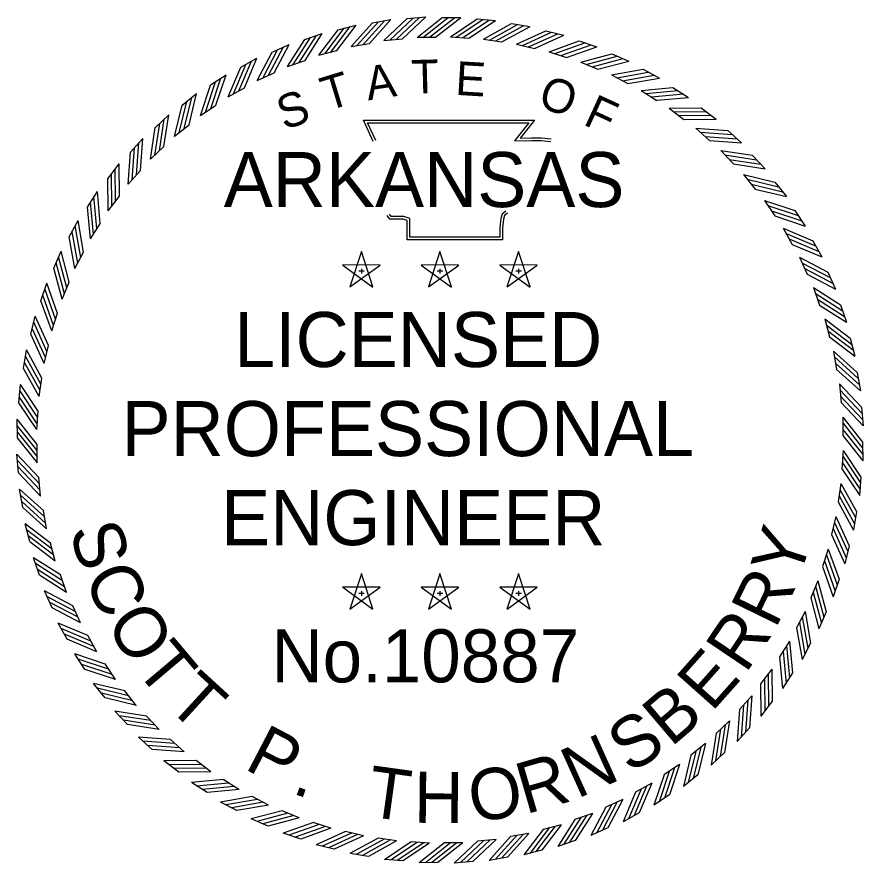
# Model space of a CAD drawing. Extents: x 155 to 3386, y 68 to 2138.
# Drawn here: x 2988.4 to 3236.8, y 328.7 to 577.1 of the extents above; entities that cross this region are included whole.
import ezdxf

# ---------------------------------------------------------------- set-up
doc = ezdxf.new("R2010")
doc.units = 0
doc.layers.add('STAMP', color=7, linetype='Continuous')

msp = doc.modelspace()

# ---------------------------------------------------------------- linework, layer by layer
at = {"layer": 'STAMP'}
for p, q in [((3102.98, 576.62), (3108.39, 577.12)), ((3113.28, 576.93), (3118.72, 576.93)), ((3123.47, 576.52), (3128.9, 576.12)), ((3082.74, 573.35), (3088.01, 574.74)), ((3092.79, 575.41), (3098.15, 576.35)), ((3133.64, 575.2), (3139.01, 574.35)), ((3072.9, 570.48), (3078.03, 572.29)), ((3143.67, 573.04), (3148.95, 571.76)), ((3063.33, 566.8), (3068.29, 569.03)), ((3086.49, 568.42), (3091.86, 569.36)), ((3096.11, 570.18), (3101.54, 570.68)), ((3105.85, 571.14), (3111.31, 571.14)), ((3115.64, 571.29), (3121.08, 570.89)), ((3125.41, 570.63), (3130.79, 569.79)), ((3135.08, 569.17), (3140.38, 567.88)), ((3153.48, 570.07), (3158.64, 568.35)), ((3077.04, 565.87), (3082.31, 567.25)), ((3144.61, 566.92), (3149.78, 565.2)), ((3054.09, 562.34), (3058.85, 564.97)), ((3067.83, 562.54), (3072.97, 564.36)), ((3163.02, 566.29), (3168.02, 564.15)), ((3153.91, 563.89), (3158.93, 561.74)), ((3172.21, 561.74), (3177.02, 559.19)), ((3045.25, 557.14), (3049.78, 560.15)), ((3058.93, 558.47), (3063.9, 560.71)), ((3162.94, 560.1), (3167.76, 557.54)), ((3036.88, 551.22), (3041.14, 554.6)), ((3050.39, 553.68), (3055.17, 556.32)), ((3171.62, 555.57), (3176.21, 552.63)), ((3180.99, 556.44), (3185.57, 553.51)), ((3042.29, 548.2), (3046.82, 551.23)), ((3179.89, 550.35), (3184.23, 547.04)), ((3189.31, 550.44), (3193.63, 547.14)), ((3029.02, 544.63), (3032.98, 548.35)), ((3034.66, 542.07), (3038.93, 545.46)), ((3187.71, 544.46), (3191.76, 540.8)), ((3197.1, 543.77), (3201.14, 540.13)), ((3021.73, 537.42), (3025.37, 541.45)), ((3027.56, 535.33), (3031.54, 539.06)), ((3195.01, 537.94), (3198.74, 533.96)), ((3204.31, 536.48), (3208.04, 532.52)), ((3015.06, 529.62), (3018.36, 533.95)), ((3021.04, 528.03), (3024.7, 532.07)), ((3201.75, 530.84), (3205.14, 526.57)), ((3210.9, 528.62), (3214.28, 524.36)), ((3009.06, 521.31), (3011.99, 525.89)), ((3015.15, 520.21), (3018.46, 524.54)), ((3207.88, 523.21), (3210.91, 518.68)), ((3216.82, 520.25), (3219.84, 515.72)), ((3003.76, 512.52), (3006.31, 517.33)), ((3009.93, 511.93), (3012.87, 516.53)), ((3213.36, 515.11), (3216, 510.33)), ((3222.02, 511.41), (3224.66, 506.65)), ((2999.21, 503.33), (3001.35, 508.34)), ((3005.4, 503.25), (3007.96, 508.07)), ((3089.5, 508.28), (3086.1, 497.84)), ((3092.89, 497.84), (3089.51, 508.29)), ((3112.58, 508.28), (3109.18, 497.84)), ((3115.97, 497.84), (3112.59, 508.29)), ((3135.66, 508.28), (3132.26, 497.84)), ((3139.05, 497.84), (3135.67, 508.29)), ((3218.16, 506.57), (3220.39, 501.6)), ((3094.99, 504.29), (3084.01, 504.3)), ((3084.02, 504.29), (3092.9, 497.83)), ((3086.11, 497.84), (3095, 504.29)), ((3088.72, 502.54), (3090.35, 502.54)), ((3089.51, 503.13), (3089.51, 501.75)), ((3118.07, 504.29), (3107.08, 504.3)), ((3107.09, 504.29), (3115.97, 497.83)), ((3109.19, 497.84), (3118.08, 504.29)), ((3111.8, 502.54), (3113.43, 502.54)), ((3112.59, 503.13), (3112.59, 501.75)), ((3141.15, 504.29), (3130.16, 504.3)), ((3130.17, 504.29), (3139.05, 497.83)), ((3132.27, 497.84), (3141.16, 504.29)), ((3134.88, 502.54), (3136.51, 502.54)), ((3135.67, 503.13), (3135.67, 501.75)), ((3226.48, 502.17), (3228.71, 497.21)), ((2995.43, 493.8), (2997.15, 498.96)), ((3001.61, 494.23), (3003.76, 499.24)), ((3222.23, 497.67), (3224.05, 492.53)), ((3230.16, 492.6), (3231.98, 487.47)), ((2998.58, 484.92), (3000.3, 490.1)), ((2992.46, 483.98), (2993.74, 489.27)), ((3225.55, 488.46), (3226.94, 483.19)), ((3233.04, 482.76), (3234.42, 477.49)), ((2996.33, 475.4), (2997.62, 480.7)), ((2990.3, 473.96), (2991.15, 479.33)), ((3228.1, 479.01), (3229.05, 473.64)), ((3235.09, 472.71), (3236.04, 467.35)), ((2994.87, 465.72), (2995.71, 471.11)), ((2988.98, 463.79), (2989.38, 469.21)), ((3229.86, 469.39), (3230.36, 463.96)), ((3236.31, 462.52), (3236.81, 457.11)), ((2994.21, 455.96), (2994.61, 461.4)), ((3230.82, 459.65), (3230.87, 454.19)), ((2988.5, 453.54), (2988.45, 458.98)), ((3236.68, 452.28), (3236.73, 446.83)), ((2994.36, 446.17), (2994.31, 451.62)), ((3230.97, 449.86), (3230.57, 444.42)), ((2988.88, 443.29), (2988.38, 448.71)), ((2995.32, 436.43), (2994.82, 441.86)), ((3230.32, 440.09), (3229.47, 434.71)), ((3236.2, 442.03), (3235.8, 436.6)), ((2990.09, 433.11), (2989.15, 438.47)), ((2997.08, 426.8), (2996.14, 432.17)), ((3228.86, 430.42), (3227.57, 425.12)), ((3234.88, 431.86), (3234.04, 426.49)), ((2992.15, 423.06), (2990.76, 428.32)), ((2999.63, 417.35), (2998.25, 422.63)), ((3226.6, 420.89), (3224.88, 415.72)), ((3232.73, 421.83), (3231.44, 416.55)), ((2995.02, 413.22), (2993.21, 418.35)), ((3002.96, 408.15), (3001.14, 413.29)), ((3089.5, 413.66), (3086.1, 403.21)), ((3092.89, 403.22), (3089.51, 413.67)), ((3112.58, 413.66), (3109.18, 403.21)), ((3115.97, 403.22), (3112.59, 413.67)), ((3135.66, 413.66), (3132.26, 403.21)), ((3139.05, 403.22), (3135.67, 413.67)), ((3223.57, 411.59), (3221.43, 406.57)), ((3229.75, 412.02), (3228.03, 406.86)), ((2998.7, 403.64), (2996.47, 408.61)), ((3094.99, 409.67), (3084.01, 409.68)), ((3084.02, 409.67), (3092.9, 403.21)), ((3086.11, 403.22), (3095, 409.67)), ((3088.72, 407.92), (3090.35, 407.92)), ((3089.51, 408.5), (3089.51, 407.12)), ((3118.07, 409.67), (3107.08, 409.68)), ((3107.09, 409.67), (3115.97, 403.21)), ((3109.19, 403.22), (3118.08, 409.67)), ((3111.8, 407.92), (3113.43, 407.92)), ((3112.59, 408.5), (3112.59, 407.12)), ((3141.15, 409.67), (3130.16, 409.68)), ((3130.17, 409.67), (3139.05, 403.21)), ((3132.27, 403.22), (3141.16, 409.67)), ((3134.88, 407.92), (3136.51, 407.92)), ((3135.67, 408.5), (3135.67, 407.12)), ((3007.03, 399.25), (3004.79, 404.22)), ((3219.78, 402.56), (3217.23, 397.74)), ((3225.97, 402.48), (3223.83, 397.48)), ((3003.16, 394.41), (3000.53, 399.17)), ((3011.82, 390.71), (3009.18, 395.48)), ((3215.25, 393.88), (3212.31, 389.29)), ((3221.42, 393.29), (3218.88, 388.48)), ((3008.36, 385.57), (3005.35, 390.1)), ((3017.3, 382.6), (3014.27, 387.14)), ((3210.03, 385.61), (3206.72, 381.27)), ((3216.13, 384.51), (3213.19, 379.93)), ((3014.28, 377.19), (3010.9, 381.45)), ((3023.43, 374.97), (3020.04, 379.25)), ((3204.14, 377.79), (3200.48, 373.74)), ((3210.13, 376.19), (3206.82, 371.87)), ((3020.87, 369.33), (3017.15, 373.3)), ((3030.17, 367.88), (3026.44, 371.85)), ((3197.62, 370.49), (3193.65, 366.76)), ((3203.46, 368.4), (3199.81, 364.36)), ((3028.08, 362.04), (3024.05, 365.69)), ((3037.47, 361.36), (3033.43, 365.02)), ((3190.53, 363.75), (3186.25, 360.36)), ((3196.17, 361.19), (3192.2, 357.46)), ((3035.88, 355.37), (3031.55, 358.68)), ((3045.29, 355.47), (3040.96, 358.78)), ((3182.9, 357.62), (3178.36, 354.59)), ((3053.57, 350.25), (3048.97, 353.19)), ((3188.31, 354.6), (3184.05, 351.22)), ((3044.19, 349.37), (3039.61, 352.31)), ((3174.79, 352.14), (3170.02, 349.5)), ((3062.25, 345.72), (3057.43, 348.27)), ((3179.93, 348.68), (3175.4, 345.66)), ((3052.98, 344.08), (3048.17, 346.62)), ((3166.25, 347.34), (3161.28, 345.11)), ((3071.27, 341.93), (3066.26, 344.07)), ((3157.35, 343.27), (3152.21, 341.45)), ((3171.09, 343.48), (3166.33, 340.84)), ((3062.17, 339.53), (3057.16, 341.67)), ((3080.58, 338.9), (3075.4, 340.62)), ((3090.1, 336.64), (3084.8, 337.93)), ((3148.15, 339.95), (3142.87, 338.56)), ((3161.86, 339.02), (3156.9, 336.79)), ((3071.7, 335.75), (3066.54, 337.47)), ((3099.78, 335.18), (3094.39, 336.03)), ((3129.07, 335.64), (3123.64, 335.14)), ((3138.7, 337.4), (3133.33, 336.45)), ((3081.52, 332.77), (3076.23, 334.06)), ((3109.54, 334.53), (3104.1, 334.93)), ((3119.33, 334.68), (3113.88, 334.63)), ((3152.28, 335.34), (3147.15, 333.52)), ((3091.54, 330.62), (3086.17, 331.46)), ((3142.44, 332.46), (3137.18, 331.08)), ((3101.71, 329.3), (3096.29, 329.7)), ((3111.96, 328.82), (3106.52, 328.77)), ((3122.21, 329.19), (3116.79, 328.69)), ((3132.39, 330.41), (3127.03, 329.46))]:
    msp.add_line(p, q, dxfattribs=at)
for points in [[(3096.11, 570.17), (3102.97, 576.62)], [(3097.85, 570.32), (3104.71, 576.76)], [(3099.73, 570.53), (3106.59, 576.98)], [(3101.54, 570.68), (3108.4, 577.13)], [(3105.85, 571.13), (3113.27, 576.92)], [(3107.6, 571.12), (3115.02, 576.91)], [(3109.49, 571.16), (3116.91, 576.95)], [(3111.3, 571.14), (3118.72, 576.93)], [(3115.63, 571.29), (3123.46, 576.52)], [(3080.55, 566.81), (3086.25, 574.3)], [(3082.3, 567.26), (3088.01, 574.74)], [(3086.48, 568.41), (3092.79, 575.4)], [(3088.21, 568.7), (3094.51, 575.69)], [(3090.06, 569.07), (3096.37, 576.06)], [(3091.85, 569.37), (3098.15, 576.36)], [(3117.38, 571.14), (3125.21, 576.37)], [(3119.27, 571.04), (3127.09, 576.27)], [(3121.07, 570.89), (3128.9, 576.12)], [(3125.4, 570.63), (3133.63, 575.2)], [(3127.13, 570.34), (3135.36, 574.91)], [(3129, 570.09), (3137.23, 574.65)], [(3130.79, 569.79), (3139.02, 574.36)], [(3071.25, 563.78), (3076.32, 571.71)], [(3072.96, 564.36), (3078.03, 572.3)], [(3077.03, 565.86), (3082.74, 573.35)], [(3078.73, 566.29), (3084.44, 573.78)], [(3135.08, 569.17), (3143.66, 573.04)], [(3136.77, 568.74), (3145.36, 572.61)], [(3138.62, 568.33), (3147.2, 572.2)], [(3140.38, 567.89), (3148.96, 571.76)], [(3063.9, 560.71), (3068.29, 569.04)], [(3067.83, 562.54), (3072.89, 570.47)], [(3069.48, 563.11), (3074.55, 571.04)], [(3144.6, 566.92), (3153.47, 570.06)], [(3146.26, 566.35), (3155.13, 569.5)], [(3148.06, 565.79), (3156.94, 568.94)], [(3058.93, 558.47), (3063.32, 566.79)], [(3060.53, 559.17), (3064.92, 567.49)], [(3062.24, 559.98), (3066.63, 568.31)], [(3149.78, 565.2), (3158.65, 568.35)], [(3053.57, 555.46), (3057.26, 564.12)], [(3055.16, 556.32), (3058.85, 564.98)], [(3153.91, 563.88), (3163.01, 566.29)], [(3155.51, 563.18), (3164.61, 565.59)], [(3157.26, 562.48), (3166.37, 564.88)], [(3158.92, 561.75), (3168.03, 564.15)], [(3050.39, 553.67), (3054.09, 562.33)], [(3051.93, 554.51), (3055.63, 563.17)], [(3162.93, 560.09), (3172.2, 561.74)], [(3045.3, 550.23), (3048.26, 559.17)], [(3046.82, 551.23), (3049.78, 560.16)], [(3164.47, 559.26), (3173.74, 560.9)], [(3166.16, 558.41), (3175.43, 560.06)], [(3167.75, 557.55), (3177.02, 559.19)], [(3042.28, 548.19), (3045.25, 557.13)], [(3043.75, 549.15), (3046.71, 558.09)], [(3038.92, 545.46), (3041.14, 554.61)], [(3171.61, 555.57), (3180.98, 556.44)], [(3173.07, 554.61), (3182.45, 555.49)], [(3174.69, 553.63), (3184.06, 554.5)], [(3036.04, 543.14), (3038.25, 552.29)], [(3037.49, 544.34), (3039.71, 553.49)], [(3176.21, 552.64), (3185.58, 553.51)], [(3034.65, 542.06), (3036.87, 551.21)], [(3179.88, 550.35), (3189.3, 550.44)], [(3181.27, 549.27), (3190.68, 549.37)], [(3030.2, 537.83), (3031.65, 547.13)], [(3031.53, 539.06), (3032.99, 548.36)], [(3093.01, 540.51), (3090.11, 546.79), (3140.29, 546.82), (3136.09, 541.56), (3139.5, 541.6), (3142.35, 541.64), (3145.2, 541.33)], [(3182.79, 548.16), (3192.21, 548.25)], [(3184.22, 547.04), (3193.64, 547.14)], [(3027.56, 535.32), (3029.01, 544.62)], [(3028.85, 536.51), (3030.3, 545.81)], [(3093.73, 540.85), (3091.35, 546), (3138.64, 546.03), (3134.43, 540.74), (3139.51, 540.81), (3142.31, 540.84), (3145.11, 540.54)], [(3187.7, 544.46), (3197.09, 543.78)], [(3188.99, 543.27), (3198.38, 542.59)], [(3190.42, 542.03), (3199.81, 541.35)], [(3023.47, 530.74), (3024.15, 540.13)], [(3024.69, 532.07), (3025.37, 541.46)], [(3191.75, 540.81), (3201.14, 540.13)], [(3021.04, 528.02), (3021.72, 537.41)], [(3022.23, 529.31), (3022.91, 538.7)], [(3195, 537.94), (3204.31, 536.49)], [(3196.19, 536.65), (3205.49, 535.2)], [(3197.51, 535.3), (3206.81, 533.85)], [(3017.34, 523.11), (3017.25, 532.52)], [(3018.46, 524.54), (3018.36, 533.95)], [(3198.74, 533.97), (3208.04, 532.51)], [(3015.15, 520.2), (3015.06, 529.61)], [(3016.23, 521.58), (3016.13, 531)], [(3201.75, 530.85), (3210.89, 528.63)], [(3202.82, 529.46), (3211.97, 527.25)], [(3204.03, 528.01), (3213.18, 525.79)], [(3011.87, 515.01), (3011, 524.38)], [(3012.86, 516.52), (3011.99, 525.9)], [(3205.14, 526.58), (3214.29, 524.36)], [(3010.89, 513.39), (3010.01, 522.76)], [(3207.88, 523.22), (3216.81, 520.25)], [(3208.83, 521.75), (3217.77, 518.79)], [(3009.93, 511.93), (3009.06, 521.3)], [(3132.38, 519.49), (3131.52, 518.79), (3131.24, 517.75), (3130.96, 515.15), (3130.96, 511.68), (3102.94, 511.68), (3102.94, 516.36), (3102.94, 517.4), (3101.81, 517.75), (3097.82, 517.75), (3097.12, 518.83)], [(3131.88, 520.1), (3130.82, 519.24), (3130.46, 517.9), (3130.16, 515.19), (3130.16, 512.47), (3103.74, 512.47), (3103.74, 516.36), (3103.74, 517.99), (3101.93, 518.54), (3098.25, 518.54), (3097.78, 519.26)], [(3209.92, 520.2), (3218.85, 517.24)], [(3007.95, 508.07), (3006.31, 517.34)], [(3210.91, 518.68), (3219.84, 515.72)], [(3007.09, 506.48), (3005.44, 515.75)], [(3213.36, 515.11), (3222.02, 511.42)], [(3005.41, 503.25), (3003.76, 512.52)], [(3006.24, 504.79), (3004.6, 514.06)], [(3214.19, 513.57), (3222.85, 509.87)], [(3215.14, 511.93), (3223.8, 508.24)], [(3216, 510.34), (3224.66, 506.65)], [(3003.75, 499.24), (3001.35, 508.34)], [(3002.32, 495.83), (2999.92, 504.93)], [(3003.02, 497.58), (3000.62, 506.68)], [(3218.15, 506.58), (3226.47, 502.18)], [(3218.85, 504.97), (3227.18, 500.58)], [(3001.62, 494.22), (2999.21, 503.32)], [(3219.67, 503.26), (3227.99, 498.87)], [(3220.39, 501.6), (3228.72, 497.21)], [(2999.71, 488.38), (2996.56, 497.25)], [(3000.3, 490.09), (2997.15, 498.97)], [(3222.22, 497.67), (3230.15, 492.61)], [(2999.15, 486.57), (2996, 495.45)], [(3222.79, 496.02), (3230.72, 490.95)], [(2998.58, 484.92), (2995.44, 493.79)], [(3223.46, 494.25), (3231.39, 489.18)], [(3224.05, 492.54), (3231.98, 487.47)], [(2997.17, 478.94), (2993.3, 487.52)], [(2997.61, 480.69), (2993.74, 489.28)], [(3225.54, 488.47), (3233.03, 482.76)], [(2996.76, 477.09), (2992.89, 485.67)], [(3225.97, 486.77), (3233.46, 481.06)], [(3226.49, 484.95), (3233.98, 479.25)], [(2996.33, 475.39), (2992.46, 483.98)], [(3226.94, 483.2), (3234.43, 477.49)], [(2995.41, 469.32), (2990.85, 477.55)], [(2995.71, 471.1), (2991.14, 479.34)], [(3228.09, 479.02), (3235.08, 472.71)], [(3228.38, 477.29), (3235.37, 470.99)], [(2995.16, 467.44), (2990.59, 475.68)], [(3228.75, 475.44), (3235.74, 469.13)], [(2994.87, 465.72), (2990.3, 473.95)], [(3229.05, 473.65), (3236.04, 467.35)], [(2994.46, 459.58), (2989.23, 467.41)], [(2994.61, 461.39), (2989.38, 469.22)], [(3229.86, 469.39), (3236.3, 462.53)], [(3230, 467.65), (3236.45, 460.79)], [(2994.36, 457.7), (2989.13, 465.52)], [(3230.22, 465.77), (3236.66, 458.91)], [(2994.21, 455.95), (2988.98, 463.78)], [(3230.36, 463.96), (3236.81, 457.1)], [(3230.82, 459.65), (3236.67, 452.28)], [(2994.31, 451.62), (2988.45, 458.99)], [(2994.31, 449.8), (2988.45, 457.17)], [(3230.82, 457.9), (3236.67, 450.53)], [(2994.37, 447.92), (2988.51, 455.29)], [(3230.88, 456.01), (3236.73, 448.64)], [(2994.37, 446.16), (2988.51, 453.53)], [(3230.88, 454.2), (3236.73, 446.83)], [(3230.97, 449.87), (3236.2, 442.04)], [(2994.82, 441.85), (2988.37, 448.71)], [(3230.82, 448.12), (3236.05, 440.29)], [(2994.97, 440.05), (2988.52, 446.91)], [(2995.18, 438.17), (2988.74, 445.03)], [(3230.73, 446.23), (3235.96, 438.41)], [(2995.33, 436.42), (2988.88, 443.29)], [(3230.58, 444.43), (3235.81, 436.6)], [(3230.31, 440.1), (3234.88, 431.87)], [(2996.13, 432.17), (2989.14, 438.47)], [(3230.03, 438.37), (3234.59, 430.14)], [(2996.43, 430.38), (2989.44, 436.68)], [(2996.8, 428.52), (2989.81, 434.83)], [(3229.77, 436.5), (3234.34, 428.27)], [(2997.09, 426.8), (2990.1, 433.1)], [(3229.47, 434.71), (3234.04, 426.48)], [(3228.85, 430.42), (3232.72, 421.84)], [(2998.24, 422.62), (2990.76, 428.33)], [(3228.42, 428.73), (3232.29, 420.14)], [(2998.69, 420.86), (2991.2, 426.57)], [(3227.57, 425.12), (3231.44, 416.54)], [(3228.02, 426.88), (3231.89, 418.3)], [(2999.21, 419.05), (2991.72, 424.75)], [(2999.64, 417.35), (2992.15, 423.05)], [(3226.6, 420.9), (3229.75, 412.03)], [(3001.14, 413.28), (2993.2, 418.35)], [(3225.47, 417.44), (3228.62, 408.56)], [(3226.03, 419.24), (3229.18, 410.37)], [(3001.72, 411.57), (2993.79, 416.63)], [(3224.89, 415.72), (3228.03, 406.85)], [(3002.39, 409.8), (2994.46, 414.87)], [(3002.96, 408.14), (2995.03, 413.21)], [(3222.86, 409.99), (3225.27, 400.89)], [(3223.57, 411.59), (3225.97, 402.49)], [(3004.79, 404.21), (2996.46, 408.61)], [(3222.16, 408.24), (3224.56, 399.13)], [(3005.52, 402.55), (2997.19, 406.95)], [(3006.33, 400.85), (2998.01, 405.24)], [(3221.43, 406.58), (3223.84, 397.47)], [(3007.03, 399.24), (2998.71, 403.64)], [(3219.78, 402.57), (3221.42, 393.3)], [(3218.94, 401.03), (3220.59, 391.76)], [(3009.18, 395.48), (3000.52, 399.17)], [(3010.04, 393.88), (3001.38, 397.58)], [(3217.23, 397.75), (3218.88, 388.48)], [(3218.1, 399.34), (3219.74, 390.07)], [(3010.99, 392.25), (3002.33, 395.94)], [(3011.83, 390.71), (3003.17, 394.4)], [(3215.25, 393.89), (3216.13, 384.52)], [(3014.27, 387.13), (3005.34, 390.1)], [(3213.31, 390.81), (3214.19, 381.44)], [(3214.3, 392.43), (3215.17, 383.05)], [(3015.27, 385.62), (3006.33, 388.58)], [(3212.32, 389.29), (3213.19, 379.92)], [(3016.35, 384.07), (3007.41, 387.03)], [(3017.31, 382.6), (3008.37, 385.57)], [(3210.03, 385.62), (3210.13, 376.2)], [(3207.84, 382.71), (3207.94, 373.29)], [(3208.95, 384.23), (3209.05, 374.82)], [(3020.04, 379.24), (3010.89, 381.46)], [(3206.73, 381.28), (3206.82, 371.86)], [(3021.16, 377.81), (3012.01, 380.03)], [(3022.36, 376.35), (3013.21, 378.57)], [(3204.14, 377.8), (3203.46, 368.41)], [(3023.44, 374.97), (3014.29, 377.19)], [(3202.95, 376.51), (3202.27, 367.12)], [(3026.44, 371.85), (3017.14, 373.3)], [(3200.49, 373.75), (3199.81, 364.36)], [(3201.72, 375.08), (3201.04, 365.69)], [(3027.67, 370.51), (3018.37, 371.97)], [(3028.99, 369.16), (3019.69, 370.62)], [(3197.63, 370.5), (3196.17, 361.19)], [(3030.18, 367.88), (3020.88, 369.33)], [(3194.99, 367.99), (3193.53, 358.69)], [(3196.34, 369.31), (3194.88, 360.01)], [(3033.43, 365.01), (3024.04, 365.69)], [(3193.65, 366.76), (3192.2, 357.46)], [(3034.76, 363.78), (3025.37, 364.46)], [(3036.19, 362.55), (3026.8, 363.23)], [(3190.53, 363.76), (3188.31, 354.61)], [(3037.48, 361.36), (3028.09, 362.04)], [(3186.26, 360.36), (3184.04, 351.21)], [(3187.69, 361.47), (3185.47, 352.32)], [(3189.15, 362.68), (3186.93, 353.53)], [(3040.96, 358.77), (3031.55, 358.68)], [(3042.39, 357.66), (3032.98, 357.56)], [(3043.92, 356.55), (3034.5, 356.45)], [(3045.3, 355.47), (3035.89, 355.37)], [(3179.89, 355.58), (3176.92, 346.65)], [(3181.43, 356.67), (3178.47, 347.73)], [(3182.9, 357.62), (3179.93, 348.69)], [(3048.98, 353.18), (3039.6, 352.31)], [(3178.37, 354.59), (3175.4, 345.66)], [(3050.49, 352.19), (3041.12, 351.31)], [(3052.11, 351.2), (3042.74, 350.33)], [(3171.62, 350.36), (3167.92, 341.7)], [(3173.25, 351.31), (3169.56, 342.65)], [(3174.79, 352.14), (3171.1, 343.48)], [(3053.58, 350.25), (3044.2, 349.37)], [(3057.43, 348.27), (3048.16, 346.62)], [(3170.02, 349.5), (3166.33, 340.84)], [(3059.02, 347.4), (3049.75, 345.76)], [(3060.71, 346.56), (3051.44, 344.91)], [(3062.25, 345.72), (3052.98, 344.08)], [(3162.95, 345.83), (3158.55, 337.51)], [(3164.65, 346.65), (3160.26, 338.32)], [(3166.26, 347.35), (3161.86, 339.03)], [(3066.26, 344.07), (3057.16, 341.66)], [(3067.92, 343.34), (3058.82, 340.94)], [(3157.36, 343.28), (3152.29, 335.35)], [(3161.29, 345.11), (3156.89, 336.78)], [(3069.67, 342.64), (3060.57, 340.23)], [(3071.28, 341.93), (3062.18, 339.53)], [(3075.41, 340.61), (3066.53, 337.47)], [(3152.22, 341.45), (3147.15, 333.52)], [(3153.93, 342.04), (3148.87, 334.11)], [(3155.7, 342.71), (3150.63, 334.78)], [(3077.12, 340.03), (3068.25, 336.88)], [(3078.93, 339.47), (3070.05, 336.32)], [(3080.58, 338.9), (3071.71, 335.75)], [(3084.81, 337.93), (3076.22, 334.06)], [(3142.88, 338.56), (3137.17, 331.07)], [(3144.64, 339.01), (3138.93, 331.52)], [(3146.45, 339.53), (3140.75, 332.04)], [(3148.15, 339.96), (3142.45, 332.47)], [(3086.56, 337.48), (3077.98, 333.61)], [(3088.41, 337.08), (3079.83, 333.21)], [(3090.11, 336.65), (3081.52, 332.78)], [(3094.4, 336.03), (3086.16, 331.46)], [(3096.18, 335.73), (3087.95, 331.16)], [(3098.06, 335.47), (3089.82, 330.91)], [(3127.33, 335.5), (3120.47, 329.05)], [(3129.08, 335.64), (3122.21, 329.2)], [(3133.33, 336.45), (3127.03, 329.46)], [(3135.12, 336.75), (3128.82, 329.76)], [(3136.98, 337.12), (3130.67, 330.13)], [(3138.7, 337.41), (3132.4, 330.42)], [(3099.78, 335.19), (3091.55, 330.62)], [(3104.11, 334.92), (3096.28, 329.69)], [(3105.92, 334.77), (3098.09, 329.54)], [(3107.8, 334.68), (3099.98, 329.45)], [(3109.55, 334.53), (3101.72, 329.3)], [(3113.88, 334.62), (3106.51, 328.77)], [(3115.7, 334.62), (3108.33, 328.77)], [(3117.58, 334.68), (3110.22, 328.83)], [(3119.34, 334.68), (3111.97, 328.83)], [(3123.65, 335.14), (3116.79, 328.69)], [(3125.45, 335.28), (3118.59, 328.84)]]:
    msp.add_lwpolyline(points, dxfattribs=at)

# ---------------------------------------------------------------- texts
for s, height, rotation, p in [('T', 9.9, 1.4789, (3104.26, 554.56)), ('E', 9.9, 356.672, (3116.93, 554.26)), ('A', 9.9, 8.6788, (3091.48, 552.59)), ('T', 9.9, 16.9015, (3079.46, 549.46)), ('O', 9.9, 341.2218, (3140.96, 550.87)), ('S', 9.9, 19.7726, (3066.87, 543.81)), ('F', 9.9, 335.3628, (3154.3, 545.65)), ('S', 15.03, 287.2223, (3003.61, 426.44)), ('Y', 15.03, 72.0481, (3217.87, 411.43)), ('C', 15.03, 294.5183, (3007.85, 412.75)), ('R', 15.03, 64.0225, (3211.06, 397.21)), ('O', 15.03, 302.1791, (3014.14, 399.07)), ('R', 15.03, 55.9969, (3202.32, 384.08)), ('T', 15.03, 310.2047, (3022.63, 385.78)), ('E', 15.03, 48.3361, (3192.36, 372.8)), ('T', 15.03, 317.5007, (3031.88, 374.83)), ('B', 15.03, 40.3105, (3180.4, 362.53)), ('S', 15.03, 33.0144, (3168.38, 354.71)), ('P', 15.03, 332.4576, (3054.78, 356.51)), ('N', 15.03, 24.2592, (3152.79, 347.45)), ('R', 15.03, 16.2336, (3137.68, 342.94)), ('T', 15.03, 352.1568, (3090.69, 342.49)), ('H', 15.03, 359.4528, (3104.89, 340.53)), ('O', 15.03, 8.208, (3122.09, 340.59)), ('.', 15.03, 340.4832, (3068.81, 349.31))]:
    msp.add_text(s, height=height, rotation=rotation, dxfattribs=at).set_placement(p)
for s, height, p in [('ARKANSAS', 16.155, (3049.09, 521.29)), ('LICENSED', 16.155, (3052.17, 474.34)), ('PROFESSIONAL', 16.1547, (3019.09, 448.18)), ('ENGINEER', 16.155, (3048.32, 422.03)), ('No.10887', 15.578, (3063.09, 381.75))]:
    msp.add_text(s, height=height, dxfattribs=at).set_placement(p)

doc.saveas('drawing.dxf')
